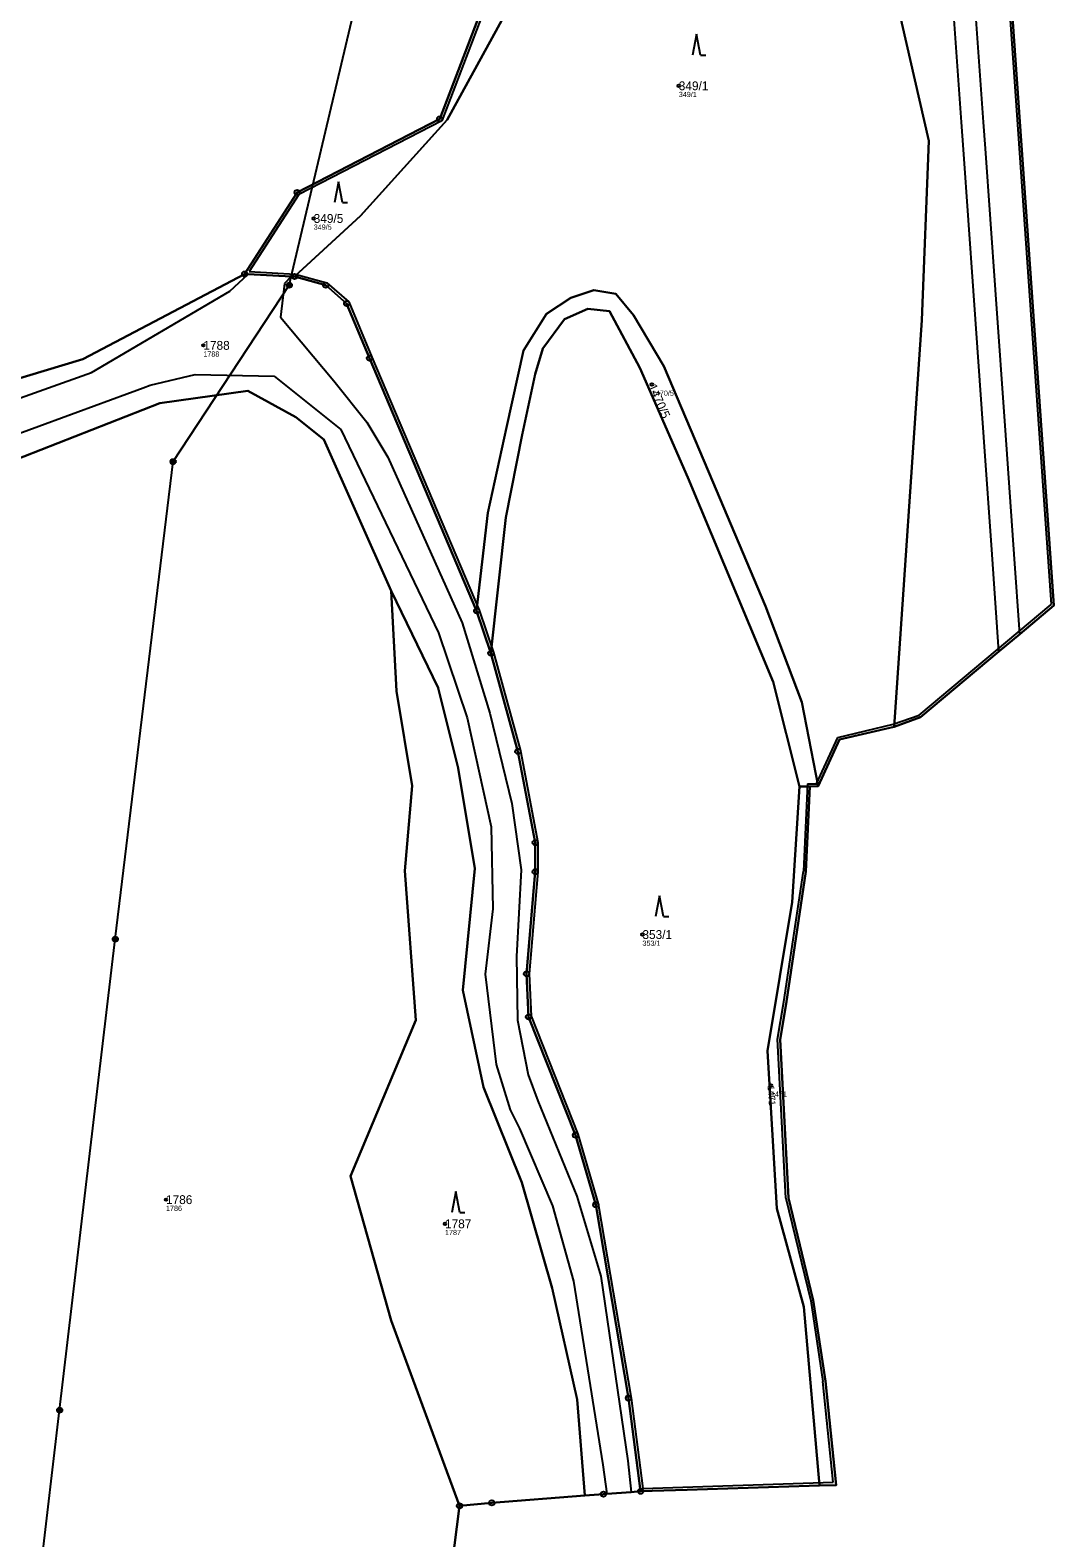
# Model space of a CAD drawing. Extents: x -770088 to -765625, y -1057899 to -1053934.
# Drawn here: x -765902.9 to -765706.4, y -1056571.8 to -1056282.3 of the extents above; entities that cross this region are included whole.
import ezdxf

# ---------------------------------------------------------------- set-up
doc = ezdxf.new("R2010")
doc.units = 0
for name, color, linetype in [('Definiční body', 7, 'Continuous'), ('Hranice parcel', 7, 'Continuous'), ('Parcelní čísla', 7, 'Continuous'), ('Polygon ku', 7, 'Continuous'), ('Polygon parcely', 7, 'Continuous'), ('Poz předměty', 7, 'Continuous'), ('Vnitřní kresba', 7, 'Continuous'), ('Značky bodu BP', 7, 'Continuous'), ('Značky kultur', 7, 'Continuous')]:
    doc.layers.add(name, color=color, linetype=linetype)

msp = doc.modelspace()

# ---------------------------------------------------------------- linework, layer by layer
at = {"layer": 'Definiční body'}
for centre in [(-765778.37, -1056293), (-765848.46, -1056318.47), (-765869.64, -1056342.83), (-765783.54, -1056350.35), (-765785.35, -1056455.95), (-765760.68, -1056484.91), (-765876.81, -1056506.84), (-765823.25, -1056511.48)]:
    msp.add_circle(centre, 0.25, dxfattribs=at)
at = {"layer": 'Hranice parcel'}
for p, q in [((-765814.44, -1056401.94), (-765817.18, -1056393.81)), ((-765706.37, -1056392.79), (-765712.9, -1056398.27)), ((-765712.9, -1056398.27), (-765716.91, -1056401.63)), ((-765755.18, -1056427.55), (-765753.21, -1056427.51)), ((-765753.21, -1056427.51), (-765753.95, -1056443.84)), ((-765751.64, -1056427.48), (-765753.21, -1056427.51)), ((-765753.95, -1056443.84), (-765757.76, -1056469.23)), ((-765757.76, -1056469.23), (-765758.89, -1056476.08)), ((-765758.89, -1056476.08), (-765757.33, -1056506.5)), ((-765753.35, -1056561.76), (-765776.79, -1056562.53)), ((-765751.35, -1056561.69), (-765753.35, -1056561.76)), ((-765748.18, -1056561.64), (-765751.35, -1056561.69)), ((-765776.79, -1056562.53), (-765785.69, -1056562.83))]:
    msp.add_line(p, q, dxfattribs=at)
for points in [[(-765729.16, -1056040.93), (-765728.73, -1056077.66), (-765726.15, -1056111.43), (-765722.95, -1056151.55), (-765715.51, -1056262.47), (-765706.37, -1056392.79)], [(-765823.25, -1056184.33), (-765811.49, -1056197.21), (-765805.06, -1056214.48), (-765811.65, -1056266.28), (-765824.27, -1056299.36), (-765851.63, -1056313.48), (-765861.72, -1056329.13)], [(-765852.12, -1056329.62), (-765839.5, -1056317.98), (-765822.84, -1056299.55), (-765810.26, -1056276.51), (-765802.81, -1056255.6), (-765796.52, -1056233.84), (-765797.92, -1056203.12), (-765798.18, -1056197.97)], [(-765737.03, -1056416.06), (-765731.72, -1056338), (-765730.39, -1056303.58), (-765737.33, -1056273.09), (-765738.73, -1056229.99)], [(-765861.72, -1056329.13), (-765892.8, -1056345.5), (-765925.28, -1056355.26), (-765960.64, -1056368.7), (-765968.29, -1056371.84)], [(-765861.72, -1056329.13), (-765861.01, -1056329.17), (-765852.77, -1056329.59), (-765852.12, -1056329.62)], [(-765817.18, -1056393.81), (-765837.73, -1056345.29), (-765842.14, -1056334.81), (-765846.15, -1056331.29), (-765852.12, -1056329.62)], [(-765817.18, -1056393.81), (-765815, -1056375), (-765811.43, -1056358.6), (-765808.2, -1056343.84), (-765803.78, -1056336.78), (-765799.09, -1056333.69), (-765794.67, -1056332.24), (-765790.44, -1056332.96), (-765787.08, -1056337.05), (-765781.27, -1056346.8), (-765772.69, -1056367.03), (-765761.73, -1056392.93), (-765754.73, -1056411.31), (-765751.64, -1056427.48)], [(-765755.18, -1056427.55), (-765760.28, -1056407.42), (-765776.65, -1056368.22), (-765785.82, -1056347.13), (-765791.7, -1056336.26), (-765795.86, -1056335.8), (-765800.34, -1056337.77), (-765804.5, -1056343.44), (-765805.93, -1056348.35), (-765808.46, -1056359.98), (-765811.59, -1056375.88), (-765814.44, -1056401.94)], [(-765833.6, -1056389.97), (-765846.49, -1056360.89), (-765851.9, -1056356.61), (-765861.12, -1056351.54), (-765878.01, -1056353.91), (-765907.34, -1056365.46)], [(-765820.45, -1056565.62), (-765833.56, -1056530.06), (-765841.37, -1056502.32), (-765828.82, -1056472.38), (-765830.94, -1056443.69), (-765829.53, -1056427.4), (-765832.58, -1056409.23), (-765833.6, -1056389.97)], [(-765796.41, -1056563.66), (-765797.91, -1056545.22), (-765802.69, -1056523.81), (-765808.51, -1056503.52), (-765815.84, -1056485.23), (-765819.84, -1056466.65), (-765817.51, -1056443.26), (-765820.75, -1056423.97), (-765824.54, -1056408.57), (-765833.6, -1056389.97)], [(-765785.69, -1056562.83), (-765788.04, -1056544.93), (-765794.31, -1056507.81), (-765798.2, -1056494.47), (-765807.21, -1056471.75), (-765807.6, -1056463.47), (-765805.93, -1056443.88), (-765805.93, -1056438.3), (-765809.26, -1056420.77), (-765814.44, -1056401.94)], [(-765716.91, -1056401.63), (-765731.95, -1056414.24), (-765737.03, -1056416.06)], [(-765737.03, -1056416.06), (-765747.52, -1056418.52), (-765751.64, -1056427.48)], [(-765751.35, -1056561.69), (-765754.38, -1056527.39), (-765759.53, -1056508.54), (-765761.36, -1056478.28), (-765756.6, -1056449.75), (-765755.18, -1056427.55)], [(-765757.33, -1056506.5), (-765752.56, -1056526.11), (-765750.2, -1056541.69), (-765748.18, -1056561.64)], [(-765796.41, -1056563.66), (-765814.26, -1056565.06), (-765820.45, -1056565.62)], [(-765785.69, -1056562.83), (-765787.54, -1056562.97), (-765792.21, -1056563.33), (-765792.85, -1056563.38), (-765796.41, -1056563.66)], [(-765820.45, -1056565.62), (-765836.08, -1056688.49), (-765828.52, -1056722.56), (-765814.74, -1056752.13)]]:
    msp.add_lwpolyline(points, dxfattribs=at)
at = {"layer": 'Polygon ku'}
msp.add_lwpolyline([(-765836.08, -1056688.49), (-765820.45, -1056565.62), (-765814.26, -1056565.06), (-765796.41, -1056563.66), (-765792.85, -1056563.38), (-765792.21, -1056563.33), (-765787.54, -1056562.97), (-765785.69, -1056562.83), (-765776.79, -1056562.53), (-765753.35, -1056561.76), (-765751.35, -1056561.69), (-765748.18, -1056561.64), (-765750.2, -1056541.69), (-765752.56, -1056526.11), (-765757.33, -1056506.5), (-765758.89, -1056476.08), (-765757.76, -1056469.23), (-765753.95, -1056443.84), (-765753.21, -1056427.51), (-765751.64, -1056427.48), (-765747.52, -1056418.52), (-765737.03, -1056416.06), (-765731.95, -1056414.24), (-765716.91, -1056401.63), (-765712.9, -1056398.27), (-765706.37, -1056392.79), (-765715.51, -1056262.47)], dxfattribs=at)
at = {"layer": 'Polygon parcely'}
for points in [[(-765839.5, -1056317.98), (-765822.84, -1056299.55), (-765810.26, -1056276.51), (-765802.81, -1056255.6), (-765796.52, -1056233.84), (-765797.92, -1056203.12), (-765798.18, -1056197.97), (-765823.25, -1056184.33), (-765811.49, -1056197.21), (-765805.06, -1056214.48), (-765811.65, -1056266.28), (-765824.27, -1056299.36), (-765851.63, -1056313.48), (-765861.72, -1056329.13), (-765861.01, -1056329.17), (-765852.77, -1056329.59), (-765852.12, -1056329.62)], [(-765753.21, -1056427.51), (-765751.64, -1056427.48), (-765754.73, -1056411.31), (-765761.73, -1056392.93), (-765772.69, -1056367.03), (-765781.27, -1056346.8), (-765787.08, -1056337.05), (-765790.44, -1056332.96), (-765794.67, -1056332.24), (-765799.09, -1056333.69), (-765803.78, -1056336.78), (-765808.2, -1056343.84), (-765811.43, -1056358.6), (-765815, -1056375), (-765817.18, -1056393.81), (-765814.44, -1056401.94), (-765811.59, -1056375.88), (-765808.46, -1056359.98), (-765805.93, -1056348.35), (-765804.5, -1056343.44), (-765800.34, -1056337.77), (-765795.86, -1056335.8), (-765791.7, -1056336.26), (-765785.82, -1056347.13), (-765776.65, -1056368.22), (-765760.28, -1056407.42), (-765755.18, -1056427.55)], [(-765755.18, -1056427.55), (-765760.28, -1056407.42), (-765776.65, -1056368.22), (-765785.82, -1056347.13), (-765791.7, -1056336.26), (-765795.86, -1056335.8), (-765800.34, -1056337.77), (-765804.5, -1056343.44), (-765805.93, -1056348.35), (-765808.46, -1056359.98), (-765811.59, -1056375.88), (-765814.44, -1056401.94), (-765809.26, -1056420.77), (-765805.93, -1056438.3), (-765805.93, -1056443.88), (-765807.6, -1056463.47), (-765807.21, -1056471.75), (-765798.2, -1056494.47), (-765794.31, -1056507.81), (-765788.04, -1056544.93), (-765785.69, -1056562.83), (-765776.79, -1056562.53), (-765753.35, -1056561.76), (-765751.35, -1056561.69), (-765754.38, -1056527.39), (-765759.53, -1056508.54), (-765761.36, -1056478.28), (-765756.6, -1056449.75)], [(-765913.55, -1056374.57), (-765911.56, -1056514.62), (-765909.49, -1056661.31), (-765908.84, -1056709.94), (-765814.74, -1056752.13), (-765828.52, -1056722.56), (-765836.08, -1056688.49), (-765820.45, -1056565.62), (-765833.56, -1056530.06), (-765841.37, -1056502.32), (-765828.82, -1056472.38), (-765830.94, -1056443.69), (-765829.53, -1056427.4), (-765832.58, -1056409.23), (-765833.6, -1056389.97), (-765846.49, -1056360.89), (-765851.9, -1056356.61), (-765861.12, -1056351.54), (-765878.01, -1056353.91), (-765907.34, -1056365.46), (-765908.27, -1056372.46)], [(-765833.6, -1056389.97), (-765832.58, -1056409.23), (-765829.53, -1056427.4), (-765830.94, -1056443.69), (-765828.82, -1056472.38), (-765841.37, -1056502.32), (-765833.56, -1056530.06), (-765820.45, -1056565.62), (-765814.26, -1056565.06), (-765796.41, -1056563.66), (-765797.91, -1056545.22), (-765802.69, -1056523.81), (-765808.51, -1056503.52), (-765815.84, -1056485.23), (-765819.84, -1056466.65), (-765817.51, -1056443.26), (-765820.75, -1056423.97), (-765824.54, -1056408.57)], [(-765755.18, -1056427.55), (-765756.6, -1056449.75), (-765761.36, -1056478.28), (-765759.53, -1056508.54), (-765754.38, -1056527.39), (-765751.35, -1056561.69), (-765748.18, -1056561.64), (-765750.2, -1056541.69), (-765752.56, -1056526.11), (-765757.33, -1056506.5), (-765758.89, -1056476.08), (-765757.76, -1056469.23), (-765753.95, -1056443.84), (-765753.21, -1056427.51)]]:
    msp.add_lwpolyline(points, close=True, dxfattribs=at)
for points in [[(-765737.33, -1056273.09), (-765730.39, -1056303.58), (-765731.72, -1056338), (-765737.03, -1056416.06), (-765731.95, -1056414.24), (-765716.91, -1056401.63), (-765712.9, -1056398.27), (-765706.37, -1056392.79), (-765715.51, -1056262.47)], [(-766194.63, -1056452.98), (-766146.47, -1056436.02), (-766129.86, -1056429.87), (-766102.14, -1056378.37), (-766034.8, -1056365.47), (-766006.46, -1056361.72), (-765978.23, -1056360.91), (-765968.29, -1056371.84), (-765960.64, -1056368.7), (-765925.28, -1056355.26), (-765892.8, -1056345.5), (-765861.72, -1056329.13), (-765851.63, -1056313.48), (-765824.27, -1056299.36), (-765811.65, -1056266.28)], [(-765810.26, -1056276.51), (-765822.84, -1056299.55), (-765839.5, -1056317.98), (-765852.12, -1056329.62), (-765846.15, -1056331.29), (-765842.14, -1056334.81), (-765837.73, -1056345.29), (-765817.18, -1056393.81), (-765815, -1056375), (-765811.43, -1056358.6), (-765808.2, -1056343.84), (-765803.78, -1056336.78), (-765799.09, -1056333.69), (-765794.67, -1056332.24), (-765790.44, -1056332.96), (-765787.08, -1056337.05), (-765781.27, -1056346.8), (-765772.69, -1056367.03), (-765761.73, -1056392.93), (-765754.73, -1056411.31), (-765751.64, -1056427.48), (-765747.52, -1056418.52), (-765737.03, -1056416.06), (-765731.72, -1056338), (-765730.39, -1056303.58), (-765737.33, -1056273.09)], [(-765907.34, -1056365.46), (-765878.01, -1056353.91), (-765861.12, -1056351.54), (-765851.9, -1056356.61), (-765846.49, -1056360.89), (-765833.6, -1056389.97), (-765824.54, -1056408.57), (-765820.75, -1056423.97), (-765817.51, -1056443.26), (-765819.84, -1056466.65), (-765815.84, -1056485.23), (-765808.51, -1056503.52), (-765802.69, -1056523.81), (-765797.91, -1056545.22), (-765796.41, -1056563.66), (-765792.85, -1056563.38), (-765792.21, -1056563.33), (-765787.54, -1056562.97), (-765785.69, -1056562.83), (-765788.04, -1056544.93), (-765794.31, -1056507.81), (-765798.2, -1056494.47), (-765807.21, -1056471.75), (-765807.6, -1056463.47), (-765805.93, -1056443.88), (-765805.93, -1056438.3), (-765809.26, -1056420.77), (-765814.44, -1056401.94), (-765817.18, -1056393.81), (-765837.73, -1056345.29), (-765842.14, -1056334.81), (-765846.15, -1056331.29), (-765852.12, -1056329.62), (-765852.77, -1056329.59), (-765861.01, -1056329.17), (-765861.72, -1056329.13), (-765892.8, -1056345.5), (-765925.28, -1056355.26)]]:
    msp.add_lwpolyline(points, dxfattribs=at)
at = {"layer": 'Poz předměty'}
for p, q in [((-765853.14, -1056331.28), (-765820.6, -1056193.3)), ((-765719.87, -1056300), (-765722.02, -1056269.73)), ((-765724.08, -1056300), (-765726.22, -1056269.87)), ((-765723.71, -1056305.22), (-765724.08, -1056300)), ((-765719.51, -1056305.06), (-765719.87, -1056300)), ((-765721.8, -1056332.36), (-765723.71, -1056305.22)), ((-765717.58, -1056332.2), (-765719.51, -1056305.06)), ((-765875.44, -1056365.15), (-765853.14, -1056331.28)), ((-765719.82, -1056360.45), (-765721.8, -1056332.36)), ((-765715.6, -1056360.08), (-765717.58, -1056332.2)), ((-765718.24, -1056382.99), (-765719.82, -1056360.45)), ((-765713.99, -1056382.89), (-765715.6, -1056360.08)), ((-765886.55, -1056456.83), (-765875.44, -1056365.15)), ((-765716.91, -1056401.63), (-765718.24, -1056382.99)), ((-765712.9, -1056398.27), (-765713.99, -1056382.89)), ((-765897.23, -1056547.27), (-765886.55, -1056456.83)), ((-765907.99, -1056638.59), (-765897.23, -1056547.27))]:
    msp.add_line(p, q, dxfattribs=at)
for centre, radius in [((-765853.14, -1056331.28), 0.5), ((-765853.14, -1056331.28), 0.4), ((-765853.14, -1056331.28), 0.3), ((-765853.14, -1056331.28), 0.2), ((-765853.14, -1056331.28), 0.1), ((-765875.44, -1056365.15), 0.5), ((-765875.44, -1056365.15), 0.4), ((-765875.44, -1056365.15), 0.3), ((-765875.44, -1056365.15), 0.2), ((-765875.44, -1056365.15), 0.1), ((-765886.55, -1056456.83), 0.5), ((-765886.55, -1056456.83), 0.4), ((-765886.55, -1056456.83), 0.3), ((-765886.55, -1056456.83), 0.2), ((-765886.55, -1056456.83), 0.1), ((-765897.23, -1056547.27), 0.5), ((-765897.23, -1056547.27), 0.4), ((-765897.23, -1056547.27), 0.3), ((-765897.23, -1056547.27), 0.2), ((-765897.23, -1056547.27), 0.1)]:
    msp.add_circle(centre, radius, dxfattribs=at)
at = {"layer": 'Vnitřní kresba'}
for p, q in [((-765716.01, -1056262.5), (-765706.89, -1056392.57)), ((-765811.16, -1056266.39), (-765823.88, -1056299.72)), ((-765823.88, -1056299.72), (-765851.28, -1056313.86)), ((-765851.28, -1056313.86), (-765860.84, -1056328.68)), ((-765864.54, -1056332.44), (-765861.01, -1056329.17)), ((-765860.84, -1056328.68), (-765852.01, -1056329.13)), ((-765852.77, -1056329.59), (-765854.04, -1056330.97)), ((-765852.01, -1056329.13), (-765845.91, -1056330.84)), ((-765891.1, -1056348.02), (-765864.54, -1056332.44)), ((-765854.04, -1056330.97), (-765854.84, -1056337.41)), ((-765845.91, -1056330.84), (-765841.73, -1056334.5)), ((-765841.73, -1056334.5), (-765837.27, -1056345.1)), ((-765854.84, -1056337.41), (-765844.6, -1056349.64)), ((-765837.27, -1056345.1), (-765816.71, -1056393.64)), ((-765930.23, -1056362.05), (-765891.1, -1056348.02)), ((-765881.19, -1056350.98), (-765879.83, -1056350.47)), ((-765879.83, -1056350.47), (-765871.24, -1056348.41)), ((-765871.24, -1056348.41), (-765856.07, -1056348.72)), ((-765856.07, -1056348.72), (-765843.26, -1056359.01)), ((-765844.6, -1056349.64), (-765838.23, -1056357.56)), ((-765928.27, -1056368.31), (-765881.19, -1056350.98)), ((-765843.26, -1056359.01), (-765824.53, -1056398.02)), ((-765838.23, -1056357.56), (-765834.25, -1056364.29)), ((-765834.25, -1056364.29), (-765819.98, -1056396.13)), ((-765816.71, -1056393.64), (-765813.96, -1056401.79)), ((-765732.21, -1056413.8), (-765706.89, -1056392.57)), ((-765819.98, -1056396.13), (-765814.62, -1056413.45)), ((-765824.53, -1056398.02), (-765818.97, -1056414.35)), ((-765813.96, -1056401.79), (-765808.77, -1056420.69)), ((-765818.97, -1056414.35), (-765814.38, -1056435.29)), ((-765814.62, -1056413.45), (-765810.4, -1056430.77)), ((-765737.19, -1056415.58), (-765732.21, -1056413.8)), ((-765747.87, -1056418.09), (-765737.19, -1056415.58)), ((-765751.96, -1056426.99), (-765747.87, -1056418.09)), ((-765808.77, -1056420.69), (-765805.43, -1056438.26)), ((-765753.69, -1056427.02), (-765754.45, -1056443.8)), ((-765753.69, -1056427.02), (-765751.96, -1056426.99)), ((-765810.4, -1056430.77), (-765808.6, -1056443.52)), ((-765814.38, -1056435.29), (-765814.08, -1056451.02)), ((-765805.43, -1056438.26), (-765805.43, -1056443.9)), ((-765808.6, -1056443.52), (-765809.54, -1056460.18)), ((-765805.43, -1056443.9), (-765807.1, -1056463.49)), ((-765758.2, -1056468.83), (-765754.45, -1056443.8)), ((-765814.08, -1056451.02), (-765815.54, -1056463.53)), ((-765809.54, -1056460.18), (-765809.35, -1056472.35)), ((-765815.54, -1056463.53), (-765813.4, -1056480.87)), ((-765807.1, -1056463.49), (-765806.72, -1056471.64)), ((-765759.39, -1056476.06), (-765758.2, -1056468.83)), ((-765809.35, -1056472.35), (-765807.3, -1056482.88)), ((-765806.72, -1056471.64), (-765797.74, -1056494.27)), ((-765757.83, -1056506.57), (-765759.39, -1056476.06)), ((-765813.4, -1056480.87), (-765810.71, -1056489.62)), ((-765807.3, -1056482.88), (-765805.42, -1056487.88)), ((-765810.71, -1056489.62), (-765808.96, -1056493.17)), ((-765805.42, -1056487.88), (-765797.95, -1056506.18)), ((-765808.96, -1056493.17), (-765802.64, -1056508.03)), ((-765797.74, -1056494.27), (-765793.83, -1056507.67)), ((-765797.95, -1056506.18), (-765793.34, -1056521.54)), ((-765757.83, -1056506.57), (-765753.04, -1056526.26)), ((-765802.64, -1056508.03), (-765798.59, -1056522.52)), ((-765793.83, -1056507.67), (-765787.53, -1056544.96)), ((-765793.34, -1056521.54), (-765788.15, -1056556.96)), ((-765798.59, -1056522.52), (-765792.93, -1056557.74)), ((-765753.04, -1056526.26), (-765750.69, -1056541.77)), ((-765748.74, -1056561.1), (-765750.69, -1056541.77)), ((-765787.53, -1056544.96), (-765785.25, -1056562.31)), ((-765792.93, -1056557.74), (-765792.21, -1056563.33)), ((-765788.15, -1056556.96), (-765787.54, -1056562.97)), ((-765785.25, -1056562.31), (-765748.74, -1056561.1))]:
    msp.add_line(p, q, dxfattribs=at)
at = {"layer": 'Značky bodu BP'}
for centre, radius in [((-765824.27, -1056299.36), 0.5), ((-765824.27, -1056299.36), 0.0303), ((-765851.63, -1056313.48), 0.5), ((-765851.63, -1056313.48), 0.0303), ((-765861.72, -1056329.13), 0.5), ((-765861.72, -1056329.13), 0.0303), ((-765852.12, -1056329.62), 0.5), ((-765852.12, -1056329.62), 0.0303), ((-765846.15, -1056331.29), 0.5), ((-765846.15, -1056331.29), 0.0303), ((-765842.14, -1056334.81), 0.5), ((-765842.14, -1056334.81), 0.0303), ((-765837.73, -1056345.29), 0.5), ((-765837.73, -1056345.29), 0.0303), ((-765817.18, -1056393.81), 0.5), ((-765817.18, -1056393.81), 0.0303), ((-765814.44, -1056401.94), 0.5), ((-765814.44, -1056401.94), 0.0303), ((-765809.26, -1056420.77), 0.5), ((-765809.26, -1056420.77), 0.0303), ((-765805.93, -1056438.3), 0.5), ((-765805.93, -1056438.3), 0.0303), ((-765805.93, -1056443.88), 0.5), ((-765805.93, -1056443.88), 0.0303), ((-765807.6, -1056463.47), 0.5), ((-765807.6, -1056463.47), 0.0303), ((-765807.21, -1056471.75), 0.5), ((-765807.21, -1056471.75), 0.0303), ((-765798.2, -1056494.47), 0.5), ((-765798.2, -1056494.47), 0.0303), ((-765794.31, -1056507.81), 0.5), ((-765794.31, -1056507.81), 0.0303), ((-765788.04, -1056544.93), 0.5), ((-765788.04, -1056544.93), 0.0303), ((-765814.26, -1056565.06), 0.5), ((-765792.85, -1056563.38), 0.5), ((-765792.85, -1056563.38), 0.0303), ((-765785.69, -1056562.83), 0.5), ((-765785.69, -1056562.83), 0.0303), ((-765820.45, -1056565.62), 0.5), ((-765820.45, -1056565.62), 0.0303), ((-765814.26, -1056565.06), 0.0303)]:
    msp.add_circle(centre, radius, dxfattribs=at)
at = {"layer": 'Značky kultur'}
for p, q in [((-765774.96, -1056283.11), (-765775.71, -1056287.11)), ((-765774.21, -1056287.11), (-765774.96, -1056283.11)), ((-765774.21, -1056287.11), (-765773.21, -1056287.11)), ((-765843.71, -1056311.43), (-765844.46, -1056315.43)), ((-765842.96, -1056315.43), (-765843.71, -1056311.43)), ((-765842.96, -1056315.43), (-765841.96, -1056315.43)), ((-765782.06, -1056448.49), (-765782.81, -1056452.49)), ((-765781.31, -1056452.49), (-765782.06, -1056448.49)), ((-765781.31, -1056452.49), (-765780.31, -1056452.49)), ((-765821.17, -1056505.28), (-765821.92, -1056509.28)), ((-765820.42, -1056509.28), (-765821.17, -1056505.28)), ((-765820.42, -1056509.28), (-765819.42, -1056509.28))]:
    msp.add_line(p, q, dxfattribs=at)

# ---------------------------------------------------------------- texts
at = {"layer": 'Definiční body'}
for s, p in [('349/1', (-765778.37, -1056295.16)), ('349/5', (-765848.46, -1056320.63)), ('1788', (-765869.64, -1056344.99)), ('1470/5', (-765783.54, -1056352.51)), ('353/1', (-765785.35, -1056458.11)), ('1471', (-765760.68, -1056487.07)), ('1786', (-765876.81, -1056509)), ('1787', (-765823.25, -1056513.64))]:
    msp.add_text(s, height=1, dxfattribs=at).set_placement(p)
at = {"layer": 'Parcelní čísla'}
for s, p in [('349/1', (-765778.37, -1056293.85)), ('349/5', (-765848.46, -1056319.32)), ('1788', (-765869.64, -1056343.68)), ('353/1', (-765785.35, -1056456.8)), ('1786', (-765876.81, -1056507.69)), ('1787', (-765823.25, -1056512.33))]:
    msp.add_text(s, height=1.7, dxfattribs=at).set_placement(p)
for s, height, rotation, p in [('1470/5', 1.7, 294, (-765784.32, -1056350.7)), ('1471', 1.3, 274, (-765761.33, -1056484.96))]:
    msp.add_text(s, height=height, rotation=rotation, dxfattribs=at).set_placement(p)

doc.saveas('drawing.dxf')
